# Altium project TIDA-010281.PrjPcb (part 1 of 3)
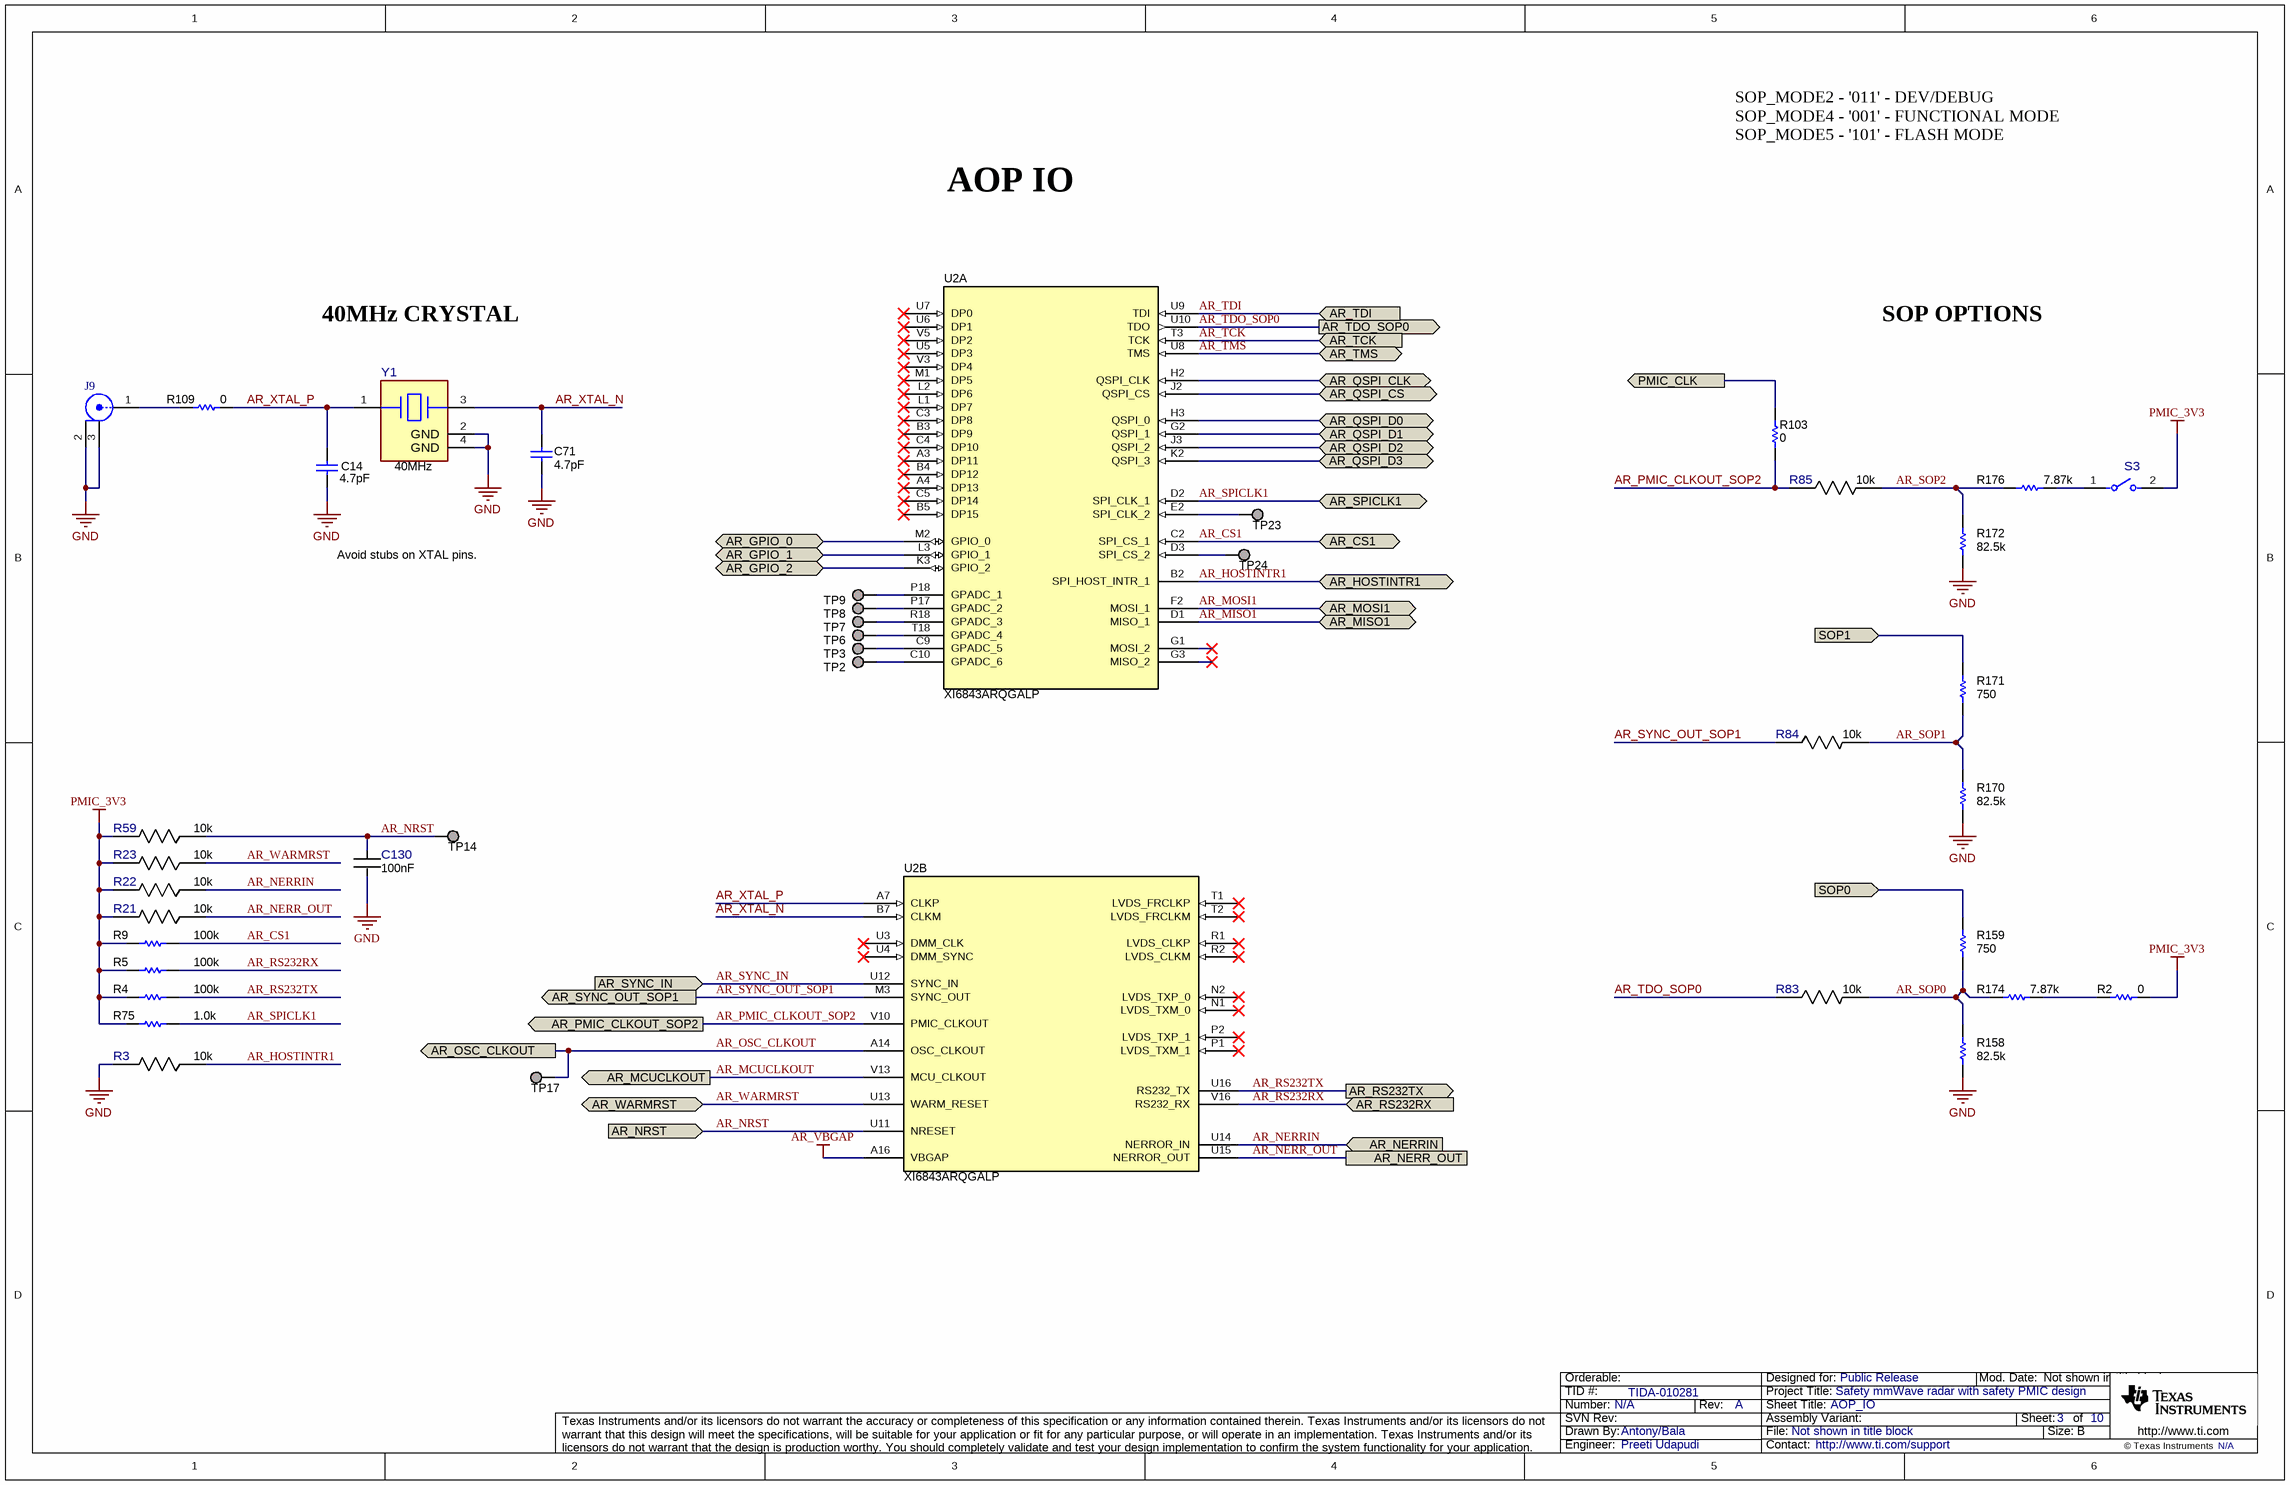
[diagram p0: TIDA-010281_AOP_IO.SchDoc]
CopyrightYear: N/A; PCB_Layout: Preeti Udapudi; PCB_Rev: A; PRJ_Customer: Public Release; PRJ_Engineer: Preeti Udapudi; PRJ_Number: N/A; PRJ_Title: Safety mmWave radar with safety PMIC design; SCH_Rev: A; TechSupport: http://www.ti.com/support; TID: TIDA-010281
10 sheets, 299 parts. Net scope: flat (ports and power ports of the same name join across sheets).
Board file: TIDA-010281.PcbDoc
Sheets:
  TIDA-010281_AOP_IO.SchDoc
  TIDA-010281_AOP_PWR.SchDoc
  TIDA-010281_BLOCK_DIAGRAM.SchDoc
  TIDA-010281_FLASH_USB_SOP.SchDoc
  TIDA-010281_Hardware.schdoc
  TIDA-010281_PMIC_BUCK.SchDoc
  TIDA-010281_RST_SWITCH.SchDoc
  TIDA-010281_TABLEOFCONTENTS.SchDoc
  TIDA-010281_XDS110_interface_1A.SchDoc
  TIDA-010281_XDS110_interface_1B.SchDoc

## Sheet TIDA-010281_AOP_IO.SchDoc: AOP_IO
size 431 x 279 mm; Date: Not shown in title block; ApprovedBy: Not shown in title block; CheckedBy: Not shown in title block; Author: Not shown in title block; CompanyName: Not shown in title block; DrawnBy: Antony/Bala; Engineer: Not shown in title block; Organization: Not shown in title block; Address1: Not shown in title block; Address2: Not shown in title block; Address3: Not shown in title block; Address4: Not shown in title block; DocumentNumber: 3; Revision: Use project parameter SCH_Rev; SheetNumber: 3; SheetTotal: 10; PageSetup: Record=PageOptions¦CenterHorizontal=True¦CenterVertical=True¦PrintScale=1.00¦XCorrection=1.00¦YCorrection=1.00¦PrintKind=0¦BorderSize=5000000¦LeftOffset=0¦BottomOffset=0¦Orientation=2¦PaperLength=1000¦PaperWidth=1000¦Scale=100¦PaperSource=15¦PrintQuality=600¦MediaType=1¦DitherType=10¦PaperKind=Letter¦PrintScaleMode=1

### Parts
C14  value 4.7pF  [0201_033L]  (hidden comment: GRM0335C1H4R7BA01D)
C71  value 4.7pF  [0201_033L]  (hidden comment: GRM0335C1H4R7BA01D)
C130  Cap_F: 100nF  [FP-GRM033R6YA104KE14D_0201 (0603 Metric)-IPC_C]  (hidden comment: GRM033R6YA104KE14D)
J9  U.FL-R-SMT-1(01)  [CONN_UFL-R-SMT-1]  (value not drawn)
R2  Res_ohm: 0  [FP-RC0201JR-070RL_0201 (0603 Metric)-MFG]  (hidden comment: RC0201JR-070RL)
R3  Res_ohm: 10k  [FP-RR0306P-103-D_0201-IPC_C]  (hidden comment: RR0306P-103-D)
R4  value 100k  [0201L]  (hidden comment: CRCW0201100KFKED)
R5  value 100k  [0201L]  (hidden comment: CRCW0201100KFKED)
R9  value 100k  [0201L]  (hidden comment: CRCW0201100KFKED)
R21  Res_ohm: 10k  [FP-RR0306P-103-D_0201-IPC_C]  (hidden comment: RR0306P-103-D)
R22  Res_ohm: 10k  [FP-RR0306P-103-D_0201-IPC_C]  (hidden comment: RR0306P-103-D)
R23  Res_ohm: 10k  [FP-RR0306P-103-D_0201-IPC_C]  (hidden comment: RR0306P-103-D)
R59  Res_ohm: 10k  [FP-RR0306P-103-D_0201-IPC_C]  (hidden comment: RR0306P-103-D)
R75  value 1.0k  [0201L]  (hidden comment: RC0201JR-071KL)
R83  Res_ohm: 10k  [FP-RR0306P-103-D_0201-IPC_C]  (hidden comment: RR0306P-103-D)
R84  Res_ohm: 10k  [FP-RR0306P-103-D_0201-IPC_C]  (hidden comment: RR0306P-103-D)
R85  Res_ohm: 10k  [FP-RR0306P-103-D_0201-IPC_C]  (hidden comment: RR0306P-103-D)
R103  Res_ohm: 0  [FP-RC0201JR-070RL_0201 (0603 Metric)-IPC_C]  (hidden comment: RC0201JR-070RL)
R109  Res_ohm: 0  [FP-RC0201JR-070RL_0201 (0603 Metric)-MFG]  (hidden comment: RC0201JR-070RL)
R158  value 82.5k  [0201L]  (hidden comment: RC0201FR-0782K5L)
R159  value 750  [0201L]  (hidden comment: RC0201JR-07750RL)
R170  value 82.5k  [0201L]  (hidden comment: RC0201FR-0782K5L)
R171  value 750  [0201L]  (hidden comment: RC0201JR-07750RL)
R172  value 82.5k  [0201L]  (hidden comment: RC0201FR-0782K5L)
R174  value 7.87k  [0201L]  (hidden comment: RC0201FR-077K87L)
R176  value 7.87k  [0201L]  (hidden comment: RC0201FR-077K87L)
S3  CHS-01TA  [FP-CHS-01TA_SMT_SW_5MM4_2MM5-MFG]  (value not drawn)
TP2  TESTPOINT  [TP_25MIL-SMT]  (value not drawn)  (no BOM)
TP3  TESTPOINT  [TP_25MIL-SMT]  (value not drawn)  (no BOM)
TP6  TESTPOINT  [TP_25MIL-SMT]  (value not drawn)  (no BOM)
TP7  TESTPOINT  [TP_25MIL-SMT]  (value not drawn)  (no BOM)
TP8  TESTPOINT  [TP_25MIL-SMT]  (value not drawn)  (no BOM)
TP9  TESTPOINT  [TP_25MIL-SMT]  (value not drawn)  (no BOM)
TP14  TESTPOINT  [TP_25MIL-SMT]  (value not drawn)  (no BOM)
TP17  TESTPOINT  [TP_25MIL-SMT]  (value not drawn)  (no BOM)
TP23  TESTPOINT  [TP_25MIL-SMT]  (value not drawn)  (no BOM)
TP24  TESTPOINT  [TP_25MIL-SMT]  (value not drawn)  (no BOM)
U2  XI6843ARQGALP  [ALP0180A]  (parts A,B of 4)
Y1  Frequency_Fixed: 40MHz  [FP-CX2016DB40000D0FLJCC_SMT_2MM0_1MM6-MFG]  (hidden comment: CX2016DB40000D0FLJCC)

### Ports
AR_CS1 (bidir), AR_GPIO_0 (bidir), AR_GPIO_1 (bidir), AR_GPIO_2 (bidir), AR_HOSTINTR1 (bidir), AR_MCUCLKOUT (out), AR_MISO1 (bidir), AR_MOSI1 (bidir), AR_NERR_OUT, AR_NERRIN (in), AR_NRST (in), AR_OSC_CLKOUT (out), AR_PMIC_CLKOUT_SOP2 (out), AR_QSPI_CLK (bidir), AR_QSPI_CS (bidir), AR_QSPI_D0 (bidir), AR_QSPI_D1 (bidir), AR_QSPI_D2 (bidir), AR_QSPI_D3 (bidir), AR_RS232RX (in), AR_RS232TX (out), AR_SPICLK1 (bidir), AR_SYNC_IN (in), AR_SYNC_OUT_SOP1 (out), AR_TCK (in), AR_TDI (in), AR_TDO_SOP0 (out), AR_TMS (bidir), AR_WARMRST (bidir), PMIC_CLK (out), SOP0 (in), SOP1 (in)

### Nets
AR_VBGAP: U2.A16(VBGAP)
GND: C14.1 C71.1 C130.2 J9.2 J9.3 R3.2 R158.1 R170.1 R172.1 Y1.2(GND) Y1.4(GND)
PMIC_3V3: R2.1 R4.1 R5.1 R9.1 R21.2 R22.2 R23.2 R59.2 R75.1 S3.2
AR_CS1: R9.2 U2.C2(SPI_CS_1) ; port AR_CS1
AR_GPIO_0: U2.M2(GPIO_0) ; port AR_GPIO_0
AR_GPIO_1: U2.L3(GPIO_1) ; port AR_GPIO_1
AR_GPIO_2: U2.K3(GPIO_2) ; port AR_GPIO_2
AR_HOSTINTR1: R3.1 U2.B2(SPI_HOST_INTR_1) ; port AR_HOSTINTR1
AR_MCUCLKOUT: U2.V13(MCU_CLKOUT) ; port AR_MCUCLKOUT
AR_MISO1: U2.D1(MISO_1) ; port AR_MISO1
AR_MOSI1: U2.F2(MOSI_1) ; port AR_MOSI1
AR_NERR_OUT: R21.1 U2.U15(NERROR_OUT) ; port AR_NERR_OUT
AR_NERRIN: R22.1 U2.U14(NERROR_IN) ; port AR_NERRIN
AR_NRST: C130.1 R59.1 TP14.1 U2.U11(NRESET) ; port AR_NRST
AR_OSC_CLKOUT: TP17.1 U2.A14(OSC_CLKOUT) ; port AR_OSC_CLKOUT
AR_PMIC_CLKOUT_SOP2: R85.1 R103.1 U2.V10(PMIC_CLKOUT) ; port AR_PMIC_CLKOUT_SOP2
AR_QSPI_CLK: U2.H2(QSPI_CLK) ; port AR_QSPI_CLK
AR_QSPI_CS: U2.J2(QSPI_CS) ; port AR_QSPI_CS
AR_QSPI_D0: U2.H3(QSPI_0) ; port AR_QSPI_D0
AR_QSPI_D1: U2.G2(QSPI_1) ; port AR_QSPI_D1
AR_QSPI_D2: U2.J3(QSPI_2) ; port AR_QSPI_D2
AR_QSPI_D3: U2.K2(QSPI_3) ; port AR_QSPI_D3
AR_RS232RX: R5.2 U2.V16(RS232_RX) ; port AR_RS232RX
AR_RS232TX: R4.2 U2.U16(RS232_TX) ; port AR_RS232TX
AR_SOP0: R83.2 R158.2 R159.1 R174.2
AR_SOP1: R84.2 R170.2 R171.1
AR_SOP2: R85.2 R172.2 R176.2
AR_SPICLK1: R75.2 U2.D2(SPI_CLK_1) ; port AR_SPICLK1
AR_SYNC_IN: U2.U12(SYNC_IN) ; port AR_SYNC_IN
AR_SYNC_OUT_SOP1: R84.1 U2.M3(SYNC_OUT) ; port AR_SYNC_OUT_SOP1
AR_TCK: U2.T3(TCK) ; port AR_TCK
AR_TDI: U2.U9(TDI) ; port AR_TDI
AR_TDO_SOP0: R83.1 U2.U10(TDO) ; port AR_TDO_SOP0
AR_TMS: U2.U8(TMS) ; port AR_TMS
AR_WARMRST: R23.1 U2.U13(WARM_RESET) ; port AR_WARMRST
AR_XTAL_N: C71.2 U2.B7(CLKM) Y1.3
AR_XTAL_P: C14.2 R109.1 U2.A7(CLKP) Y1.1
PMIC_CLK: R103.2 ; port PMIC_CLK
SOP0: R159.2 ; port SOP0
SOP1: R171.2 ; port SOP1
NetJ9_1: J9.1 R109.2
NetR2_2: R2.2 R174.1
NetR176_1: R176.1 S3.1
NetTP2_1: TP2.1 U2.C10(GPADC_6)
NetTP3_1: TP3.1 U2.C9(GPADC_5)
NetTP6_1: TP6.1 U2.T18(GPADC_4)
NetTP7_1: TP7.1 U2.R18(GPADC_3)
NetTP8_1: TP8.1 U2.P17(GPADC_2)
NetTP9_1: TP9.1 U2.P18(GPADC_1)
NetTP23_1: TP23.1 U2.E2(SPI_CLK_2)
NetTP24_1: TP24.1 U2.D3(SPI_CS_2)

Not connected (* = marked no-connect by the designer): U2 A3(DP11)* A4(DP13)* B3(DP9)* B4(DP12)* B5(DP15)* C3(DP8)* C4(DP10)* C5(DP14)* G1(MOSI_2)* G3(MISO_2)* L1(DP7)* L2(DP6)* M1(DP5)* N1(LVDS_TXM_0)* N2(LVDS_TXP_0)* P1(LVDS_TXM_1)* P2(LVDS_TXP_1)* R1(LVDS_CLKP)* R2(LVDS_CLKM)* T1(LVDS_FRCLKP)* T2(LVDS_FRCLKM)* U3(DMM_CLK)* U4(DMM_SYNC)* U5(DP3)* U6(DP1)* U7(DP0)* V3(DP4)* V5(DP2)*

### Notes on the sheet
- SOP_MODE2 - '011' - DEV/DEBUG
  SOP_MODE4 - '001' - FUNCTIONAL MODE
  SOP_MODE5 - '101' - FLASH MODE
- AOP IO
- 40MHz CRYSTAL
- SOP OPTIONS
- Avoid stubs on XTAL pins.

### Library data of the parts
C14 C71 = CMP-0080076-1: CAP, CERM, 4.7 pF, 50 V,+/- 3%, C0G/NP0, 0201; Manufacturer: MuRata; AEC Category: Q200; AEC Qualified: N; Cap_Case: 0201; SizeArea_mm2: 0.18; SizeAreaWB_mm2: 2.08; SizeX_mm: 0.6; SizeY_mm: 0.3; SizeZ_mm: 0.33; TaMax_C: 125°C; TaMin_C: -55°C; U/M: EA; Value2: 50V
C130 = CMP-0086440-1: Cap Ceramic 0.1uF 35V X5R 10% Pad SMD 0201 85C T/R; Manufacturer: Murata Electronics North America; AEC Qualified: No; SizeZ_mm: 0.33mm; Symbol Name: SYM-GRM033R6YA104KE14D; TempCo: 15%
J9 = CMP-0075320-1: Receptacle, Ultra Miniature Coaxial, Male Pin, 50 ohm, SMT; Manufacturer: Hirose Electric Co. Ltd.; CNHeader: False; Gender: Female; ContactFinish: Gold
R2 R103 R109 = CMP-0086442-2: RES SMD 0 OHM JUMPER 1/20W 0201; Manufacturer: Yageo; AEC Qualified: No; Power_W: 50mW; SizeZ_mm: 0.26mm; TempCo: 200ppm/°C; Tolerance_%: 5%; VDC_V: 25V
R3 R21-R23 R59 R83-R85 = CMP-0088002-1: 10 kOhms ±0.5% 0.05W, 1/20W Chip Resistor 0201 (0603 Metric)  Thin Film; Manufacturer: Susumu; AEC Qualified: No; Power_W: 50mW; SizeZ_mm: 0.26mm; Symbol Name: SYM-RR0306P-103-D; TempCo: 25ppm/°C; VDC_V: 15V
R4 R5 R9 = CMP-0027261-3: RES, 100 k, 1%, 0.05 W, 0201; Manufacturer: Vishay-Dale; AEC Category: Q200; AEC Qualified: N; EIA_Code: E96; Power_W: 50mW; SizeArea_mm2: 0.18; SizeX_mm: 0.6; SizeY_mm: 0.3; SizeZ_mm: 0.26; TempCo: 100 ppm/C; Value2: 0.05W; VDC_V: 30V
R75 = CMP-0027052-1: RES, 1.0 k, 5%, 0.05 W, 0201; Manufacturer: Yageo America; AEC Category: Q200; AEC Qualified: N; EIA_Code: E24; Power_W: 50mW; Res_ohm: 1k; SizeArea_mm2: 0.18; SizeX_mm: 0.6; SizeY_mm: 0.3; SizeZ_mm: 0.26; TempCo: 200 ppm/C; U/M: EA; Value2: 0.05W; Value_Code: 1k00; VDC_V: 25V
R158 R170 R172 = CMP-0027891-1: RES, 82.5 k, 1%, 0.05 W, 0201; Manufacturer: Yageo America; AEC Category: Q200; AEC Qualified: N; EIA_Code: E96; Power_W: 50mW; SizeArea_mm2: 0.18; SizeX_mm: 0.6; SizeY_mm: 0.3; SizeZ_mm: 0.26; TempCo: 200 ppm/C; U/M: EA; Value2: 0.05W; Value_Code: 82k5; VDC_V: 25V
R159 R171 = CMP-0027165-1: RES, 750, 5%, 0.05 W, 0201; Manufacturer: Yageo America; AEC Category: Q200; AEC Qualified: N; EIA_Code: E24; Power_W: 50mW; SizeArea_mm2: 0.18; SizeX_mm: 0.6; SizeY_mm: 0.3; SizeZ_mm: 0.26; TempCo: 200 ppm/C; U/M: EA; Value2: 0.05W; Value_Code: 750R; VDC_V: 25V
R174 R176 = CMP-0027880-1: RES, 7.87 k, 1%, 0.05 W, 0201; Manufacturer: Yageo America; AEC Category: Q200; AEC Qualified: N; EIA_Code: E96; Power_W: 50mW; SizeArea_mm2: 0.18; SizeX_mm: 0.6; SizeY_mm: 0.3; SizeZ_mm: 0.26; TempCo: 200 ppm/C; U/M: EA; Value2: 0.05W; Value_Code: 7k87; VDC_V: 25V
S3 = CMP-0087181-1: SWITCH SLIDE DIP SPST 100MA 6V; Manufacturer: Nidec Copal Electronics; PositionCount: 1; SizeZ_mm: 2.5mm; Symbol Name: SYM-CHS-01TA
TP2 TP3 TP6-TP9 TP14 TP17 TP23 TP24 = CMP-0078143-3: TEST POINT.  No entry in BOM.
U2 = CMP-0860942-2: XI6843ARQGALP, ALP0180A (BGA-180); Manufacturer: Texas Instruments; SizeZ_mm: 0.965; SizeX_mm: 15; AEC Qualified: N; SizeArea_mm2: 225; SizeAreaWB_mm2: 289; CompType: IC; AEC Category: Q200
Y1 = CMP-0087164-1: CRYSTAL 40.0000MHZ 8PF SMD; Manufacturer: Kyocera International Inc. Electronic Components; AEC Qualified: No; Frequency Stability: 15ppm; SizeZ_mm: 0.45mm

## Sheet TIDA-010281_AOP_PWR.SchDoc: AOP_POWER
size 431 x 279 mm; Date: Not shown in title block; ApprovedBy: Not shown in title block; CheckedBy: Not shown in title block; Author: Not shown in title block; CompanyName: Not shown in title block; DrawnBy: Antony/Bala; Engineer: Not shown in title block; Organization: Not shown in title block; Address1: Not shown in title block; Address2: Not shown in title block; Address3: Not shown in title block; Address4: Not shown in title block; DocumentNumber: 4; Revision: Use project parameter SCH_Rev; SheetNumber: 4; SheetTotal: 10; PageSetup: Record=PageOptions¦CenterHorizontal=True¦CenterVertical=True¦PrintScale=1.00¦XCorrection=1.00¦YCorrection=1.00¦PrintKind=0¦BorderSize=5000000¦LeftOffset=0¦BottomOffset=0¦Orientation=2¦PaperLength=1000¦PaperWidth=1000¦Scale=100¦PaperSource=15¦PrintQuality=600¦MediaType=1¦DitherType=10¦PaperKind=Letter¦PrintScaleMode=1
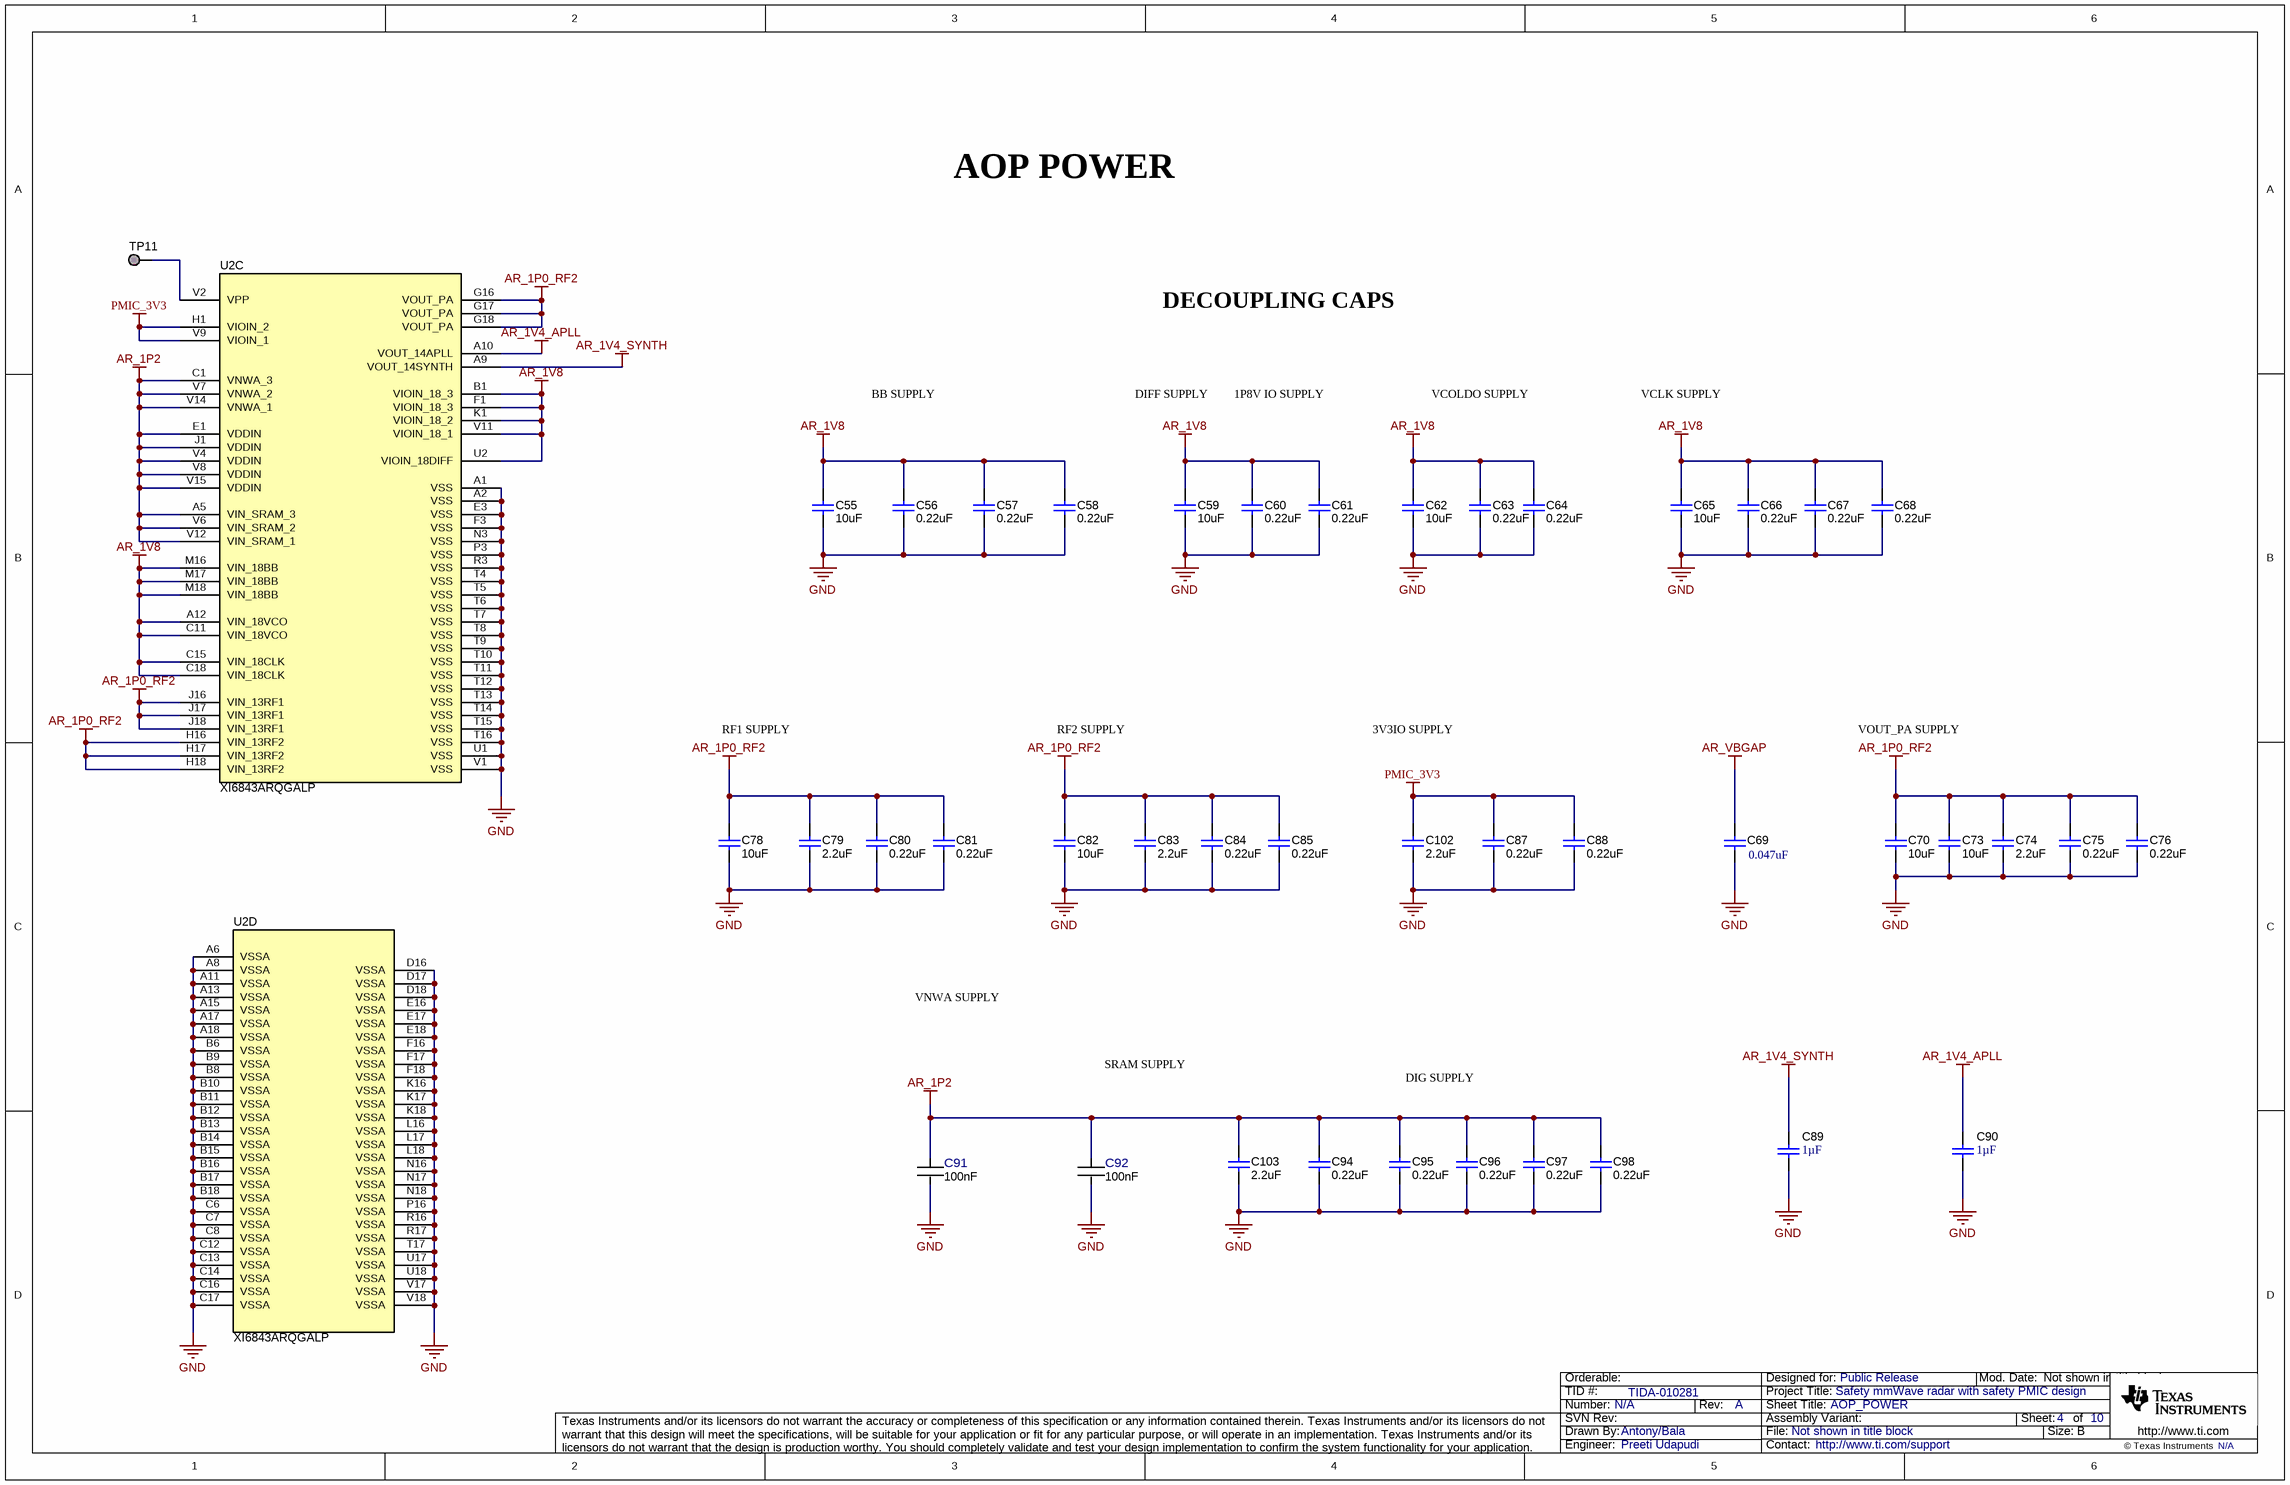
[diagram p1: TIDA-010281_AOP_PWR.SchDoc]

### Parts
C55  value 10uF  [0402_070]  (hidden comment: CL05A106MP5NUNC)
C56  value 0.22uF  [0201_033L]  (hidden comment: LMK063BJ224MP-F)
C57  value 0.22uF  [0201_033L]  (hidden comment: LMK063BJ224MP-F)
C58  value 0.22uF  [0201_033L]  (hidden comment: LMK063BJ224MP-F)
C59  value 10uF  [0402_070]  (hidden comment: CL05A106MP5NUNC)
C60  value 0.22uF  [0201_033L]  (hidden comment: LMK063BJ224MP-F)
C61  value 0.22uF  [0201_033L]  (hidden comment: LMK063BJ224MP-F)
C62  value 10uF  [0402_070]  (hidden comment: CL05A106MP5NUNC)
C63  value 0.22uF  [0201_033L]  (hidden comment: LMK063BJ224MP-F)
C64  value 0.22uF  [0201_033L]  (hidden comment: LMK063BJ224MP-F)
C65  value 10uF  [0402_070]  (hidden comment: CL05A106MP5NUNC)
C66  value 0.22uF  [0201_033L]  (hidden comment: LMK063BJ224MP-F)
C67  value 0.22uF  [0201_033L]  (hidden comment: LMK063BJ224MP-F)
C68  value 0.22uF  [0201_033L]  (hidden comment: LMK063BJ224MP-F)
C69  ValueDisplayed: 0.047uF  [0201_033L]  (hidden comment: GRM033R61C473KE84D)
C70  value 10uF  [0402_070]  (hidden comment: CL05A106MP5NUNC)
C73  value 10uF  [0402_070]  (hidden comment: CL05A106MP5NUNC)
C74  value 2.2uF  [0201L]  (hidden comment: CL03A225MQ3CRNC)
C75  value 0.22uF  [0201_033L]  (hidden comment: LMK063BJ224MP-F)
C76  value 0.22uF  [0201_033L]  (hidden comment: LMK063BJ224MP-F)
C78  value 10uF  [0402_070]  (hidden comment: CL05A106MP5NUNC)
C79  value 2.2uF  [0201L]  (hidden comment: CL03A225MQ3CRNC)
C80  value 0.22uF  [0201_033L]  (hidden comment: LMK063BJ224MP-F)
C81  value 0.22uF  [0201_033L]  (hidden comment: LMK063BJ224MP-F)
C82  value 10uF  [0402_070]  (hidden comment: CL05A106MP5NUNC)
C83  value 2.2uF  [0201L]  (hidden comment: CL03A225MQ3CRNC)
C84  value 0.22uF  [0201_033L]  (hidden comment: LMK063BJ224MP-F)
C85  value 0.22uF  [0201_033L]  (hidden comment: LMK063BJ224MP-F)
C87  value 0.22uF  [0201_033L]  (hidden comment: LMK063BJ224MP-F)
C88  value 0.22uF  [0201_033L]  (hidden comment: LMK063BJ224MP-F)
C89  ValueDisplayed: 1µF  [0402L]  (hidden comment: CGB2A1X6S0J105K033BC)
C90  ValueDisplayed: 1µF  [0402L]  (hidden comment: CGB2A1X6S0J105K033BC)
C91  Cap_F: 100nF  [FP-GRM033R6YA104KE14D_0201 (0603 Metric)-IPC_C]  (hidden comment: GRM033R6YA104KE14D)
C92  Cap_F: 100nF  [FP-GRM033R6YA104KE14D_0201 (0603 Metric)-IPC_C]  (hidden comment: GRM033R6YA104KE14D)
C94  value 0.22uF  [0201_033L]  (hidden comment: LMK063BJ224MP-F)
C95  value 0.22uF  [0201_033L]  (hidden comment: LMK063BJ224MP-F)
C96  value 0.22uF  [0201_033L]  (hidden comment: LMK063BJ224MP-F)
C97  value 0.22uF  [0201_033L]  (hidden comment: LMK063BJ224MP-F)
C98  value 0.22uF  [0201_033L]  (hidden comment: LMK063BJ224MP-F)
C102  value 2.2uF  [0201L]  (hidden comment: CL03A225MQ3CRNC)
C103  value 2.2uF  [0201L]  (hidden comment: CL03A225MQ3CRNC)
TP11  TP_SM_1MM  [TP_SM_1MM]  (value not drawn)  (no BOM)
U2  XI6843ARQGALP  [ALP0180A]  (parts C,D of 4)

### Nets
AR_1P0_RF2: C70.1 C73.1 C74.1 C75.1 C76.1 C78.1 C79.1 C80.1 C81.1 C82.1 C83.1 C84.1 C85.1 U2.G16(VOUT_PA) U2.G17(VOUT_PA) U2.G18(VOUT_PA) U2.H16(VIN_13RF2) U2.H17(VIN_13RF2) U2.H18(VIN_13RF2) U2.J16(VIN_13RF1) U2.J17(VIN_13RF1) U2.J18(VIN_13RF1)
AR_1P2: C91.1 C92.1 C94.1 C95.1 C96.1 C97.1 C98.1 C103.1 U2.A5(VIN_SRAM_3) U2.C1(VNWA_3) U2.E1(VDDIN) U2.J1(VDDIN) U2.V4(VDDIN) U2.V6(VIN_SRAM_2) U2.V7(VNWA_2) U2.V8(VDDIN) U2.V12(VIN_SRAM_1) U2.V14(VNWA_1) U2.V15(VDDIN)
AR_1V4_APLL: C90.1 U2.A10(VOUT_14APLL)
AR_1V4_SYNTH: C89.1 U2.A9(VOUT_14SYNTH)
AR_1V8: C55.1 C56.1 C57.1 C58.1 C59.1 C60.1 C61.1 C62.1 C63.1 C64.1 C65.1 C66.1 C67.1 C68.1 U2.A12(VIN_18VCO) U2.B1(VIOIN_18_3) U2.C11(VIN_18VCO) U2.C15(VIN_18CLK) U2.C18(VIN_18CLK) U2.F1(VIOIN_18_3) U2.K1(VIOIN_18_2) U2.M16(VIN_18BB) U2.M17(VIN_18BB) U2.M18(VIN_18BB) U2.U2(VIOIN_18DIFF) U2.V11(VIOIN_18_1)
AR_VBGAP: C69.1
GND: C55.2 C56.2 C57.2 C58.2 C59.2 C60.2 C61.2 C62.2 C63.2 C64.2 C65.2 C66.2 C67.2 C68.2 C69.2 C70.2 C73.2 C74.2 C75.2 C76.2 C78.2 C79.2 C80.2 C81.2 C82.2 C83.2 C84.2 C85.2 C87.2 C88.2 C89.2 C90.2 C91.2 C92.2 C94.2 C95.2 C96.2 C97.2 C98.2 C102.2 C103.2 U2.A1(VSS) U2.A2(VSS) U2.A6(VSSA) U2.A8(VSSA) U2.A11(VSSA) U2.A13(VSSA) U2.A15(VSSA) U2.A17(VSSA) U2.A18(VSSA) U2.B6(VSSA) U2.B8(VSSA) U2.B9(VSSA) U2.B10(VSSA) U2.B11(VSSA) U2.B12(VSSA) U2.B13(VSSA) U2.B14(VSSA) U2.B15(VSSA) U2.B16(VSSA) U2.B17(VSSA) U2.B18(VSSA) U2.C6(VSSA) U2.C7(VSSA) U2.C8(VSSA) U2.C12(VSSA) U2.C13(VSSA) U2.C14(VSSA) U2.C16(VSSA) U2.C17(VSSA) U2.D16(VSSA) U2.D17(VSSA) U2.D18(VSSA) U2.E3(VSS) U2.E16(VSSA) U2.E17(VSSA) U2.E18(VSSA) U2.F3(VSS) U2.F16(VSSA) U2.F17(VSSA) U2.F18(VSSA) U2.K16(VSSA) U2.K17(VSSA) U2.K18(VSSA) U2.L16(VSSA) U2.L17(VSSA) U2.L18(VSSA) U2.N3(VSS) U2.N16(VSSA) U2.N17(VSSA) U2.N18(VSSA) U2.P3(VSS) U2.P16(VSSA) U2.R3(VSS) U2.R16(VSSA) U2.R17(VSSA) U2.T4(VSS) U2.T5(VSS) U2.T6(VSS) U2.T7(VSS) U2.T8(VSS) U2.T9(VSS) U2.T10(VSS) U2.T11(VSS) U2.T12(VSS) U2.T13(VSS) U2.T14(VSS) U2.T15(VSS) U2.T16(VSS) U2.T17(VSSA) U2.U1(VSS) U2.U17(VSSA) U2.U18(VSSA) U2.V1(VSS) U2.V17(VSSA) U2.V18(VSSA)
PMIC_3V3: C87.1 C88.1 C102.1 U2.H1(VIOIN_2) U2.V9(VIOIN_1)
NetTP11_1: TP11.1 U2.V2(VPP)

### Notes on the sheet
- AOP POWER
- DECOUPLING CAPS
- BB SUPPLY
- DIFF SUPPLY
- 1P8V IO SUPPLY
- VCOLDO SUPPLY
- VCLK SUPPLY
- RF1 SUPPLY
- RF2 SUPPLY
- 3V3IO SUPPLY
- VOUT_PA SUPPLY
- VNWA SUPPLY
- SRAM SUPPLY
- DIG SUPPLY

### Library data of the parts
C55 C59 C62 C65 C70 C73 C78 C82 = CMP-0006339-4: CAP, CERM, 10 uF, 10 V, +/- 20%, X5R, 0402; Manufacturer: Samsung Electro-Mechanics; AEC Category: Q200; AEC Qualified: N; Cap_Case: 0402; Cap_F: 10µF; SizeArea_mm2: 0.5; SizeAreaWB_mm2: 3; SizeX_mm: 1; SizeZ_mm: 0.6; TaMax_C: 85°C; TaMin_C: -55°C; U/M: EA; Value1: Unknown; Value2: 10V
C56-C58 C60 C61 C63 C64 C66-C68 C75 C76 C80 C81 C84 C85 C87 C88 C94-C98 = CMP-0009781-1: CAP, CERM, 0.22 uF, 10 V, +/- 20%, X5R, 0201; Manufacturer: Taiyo Yuden; AEC Category: Q200; AEC Qualified: N; Cap_Case: 0201; Cap_F: 220nF; SizeArea_mm2: 0.18; SizeAreaWB_mm2: 2.08; SizeX_mm: 0.6; SizeY_mm: 0.3; SizeZ_mm: 0.33; TaMax_C: 85°C; TaMin_C: -55°C; U/M: EA; Value1: Unknown; Value2: 10V
C69 = CMP-0009718-2: CAP, CERM, 0.047 uF, 16 V, +/- 10%, X5R, 0201; Manufacturer: MuRata; TaMin_C: -55°C; Polarized: N; SizeAreaWB_mm2: 2.08; Value1: Unknown; U/M: EA; TaMax_C: 85°C; SizeZ_mm: 0.33; SizeX_mm: 0.6; SizeY_mm: 0.3; Cap_Case: 0201; Value2: 16V; SizeArea_mm2: 0.18; Cap_F: 47nF; AEC Category: Q200
C74 C79 C83 C102 C103 = CMP-0009657-3: CAP, CERM, 2.2 uF, 6.3 V, +/- 20%, X5R, 0201; Manufacturer: Samsung Electro-Mechanics; AEC Category: Q200; Cap_Case: 0201; Cap_F: 2.2µF; Polarized: N; SizeArea_mm2: 0.18; SizeAreaWB_mm2: 2.08; SizeX_mm: 0.6; SizeY_mm: 0.3; SizeZ_mm: 0.26; TaMax_C: 85°C; TaMin_C: -55°C; U/M: EA; Value1: Unknown; Value2: 6.3V
C89 C90 = CMP-0081763-1: CAP, CERM, 1 µF, 6.3 V,+/- 10%, X6S, 0402; Manufacturer: TDK; TaMin_C: -55°C; Polarized: N; SizeAreaWB_mm2: 3; U/M: EA; Value: 1uF; TaMax_C: 105°C; SizeZ_mm: 0.6; SizeX_mm: 1; SizeY_mm: 0.5; Cap_Case: 0402; Value2: 6.3V; CompType: Capacitor; AEC Category: Q200
C91 C92 = CMP-0086440-1: as C130 on sheet TIDA-010281_AOP_IO
TP11 = CMP-0003825-1: 1mm Test Point, SMT; Manufacturer: Any
U2 = CMP-0860942-2: as U2 on sheet TIDA-010281_AOP_IO

## Sheet TIDA-010281_BLOCK_DIAGRAM.SchDoc: BLOCK_DIAGRAM
size 431 x 279 mm; Date: Not shown in title block; ApprovedBy: Not shown in title block; CheckedBy: Not shown in title block; Author: Not shown in title block; CompanyName: Not shown in title block; DrawnBy: Antony/Bala; Engineer: Not shown in title block; Organization: Not shown in title block; Address1: Not shown in title block; Address2: Not shown in title block; Address3: Not shown in title block; Address4: Not shown in title block; DocumentNumber: 1; Revision: Use project parameter SCH_Rev; SheetNumber: 1; SheetTotal: 10; PageSetup: Record=PageOptions¦CenterHorizontal=True¦CenterVertical=True¦PrintScale=1.00¦XCorrection=1.00¦YCorrection=1.00¦PrintKind=0¦BorderSize=5000000¦LeftOffset=0¦BottomOffset=0¦Orientation=2¦PaperLength=1000¦PaperWidth=1000¦Scale=100¦PaperSource=15¦PrintQuality=600¦MediaType=1¦DitherType=10¦PaperKind=Letter¦PrintScaleMode=1
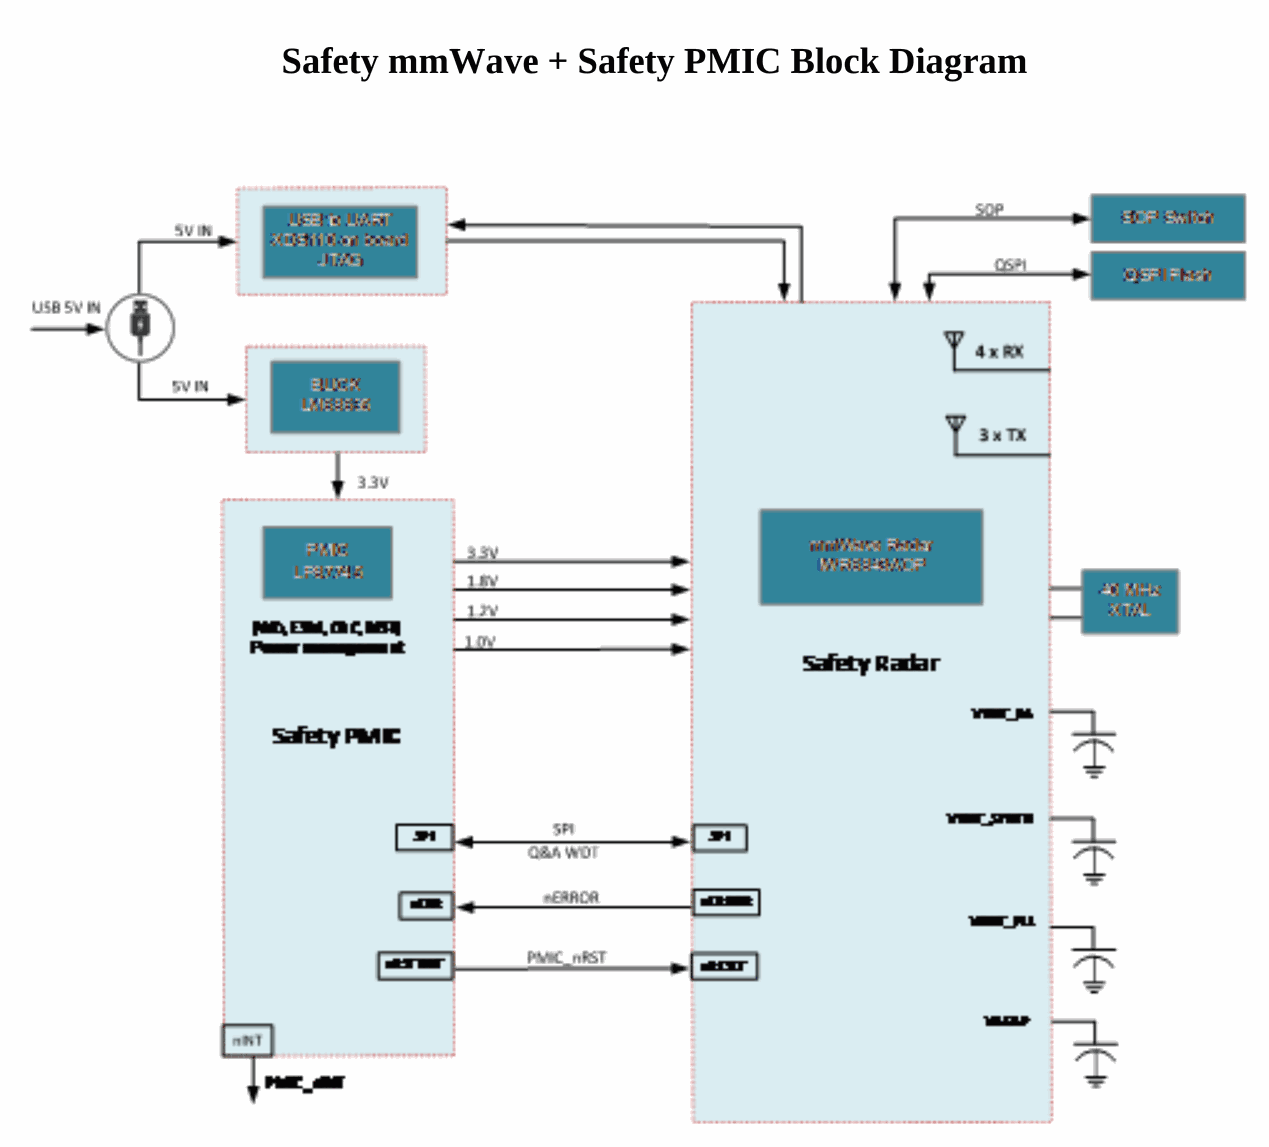
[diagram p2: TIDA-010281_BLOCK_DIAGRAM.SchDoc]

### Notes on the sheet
- Safety mmWave + Safety PMIC Block Diagram

## Sheet TIDA-010281_FLASH_USB_SOP.SchDoc: FLASH&USB_TO_UART
size 431 x 279 mm; Date: Not shown in title block; ApprovedBy: Not shown in title block; CheckedBy: Not shown in title block; Author: Not shown in title block; CompanyName: Not shown in title block; DrawnBy: Antony/Bala; Engineer: Not shown in title block; Organization: Not shown in title block; Address1: Not shown in title block; Address2: Not shown in title block; Address3: Not shown in title block; Address4: Not shown in title block; DocumentNumber: 6; Revision: Use project parameter SCH_Rev; SheetNumber: 6; SheetTotal: 10; PageSetup: Record=PageOptions¦CenterHorizontal=True¦CenterVertical=True¦PrintScale=1.00¦XCorrection=1.00¦YCorrection=1.00¦PrintKind=0¦BorderSize=5000000¦LeftOffset=0¦BottomOffset=0¦Orientation=2¦PaperLength=1000¦PaperWidth=1000¦Scale=100¦PaperSource=15¦PrintQuality=600¦MediaType=1¦DitherType=10¦PaperKind=Letter¦PrintScaleMode=1
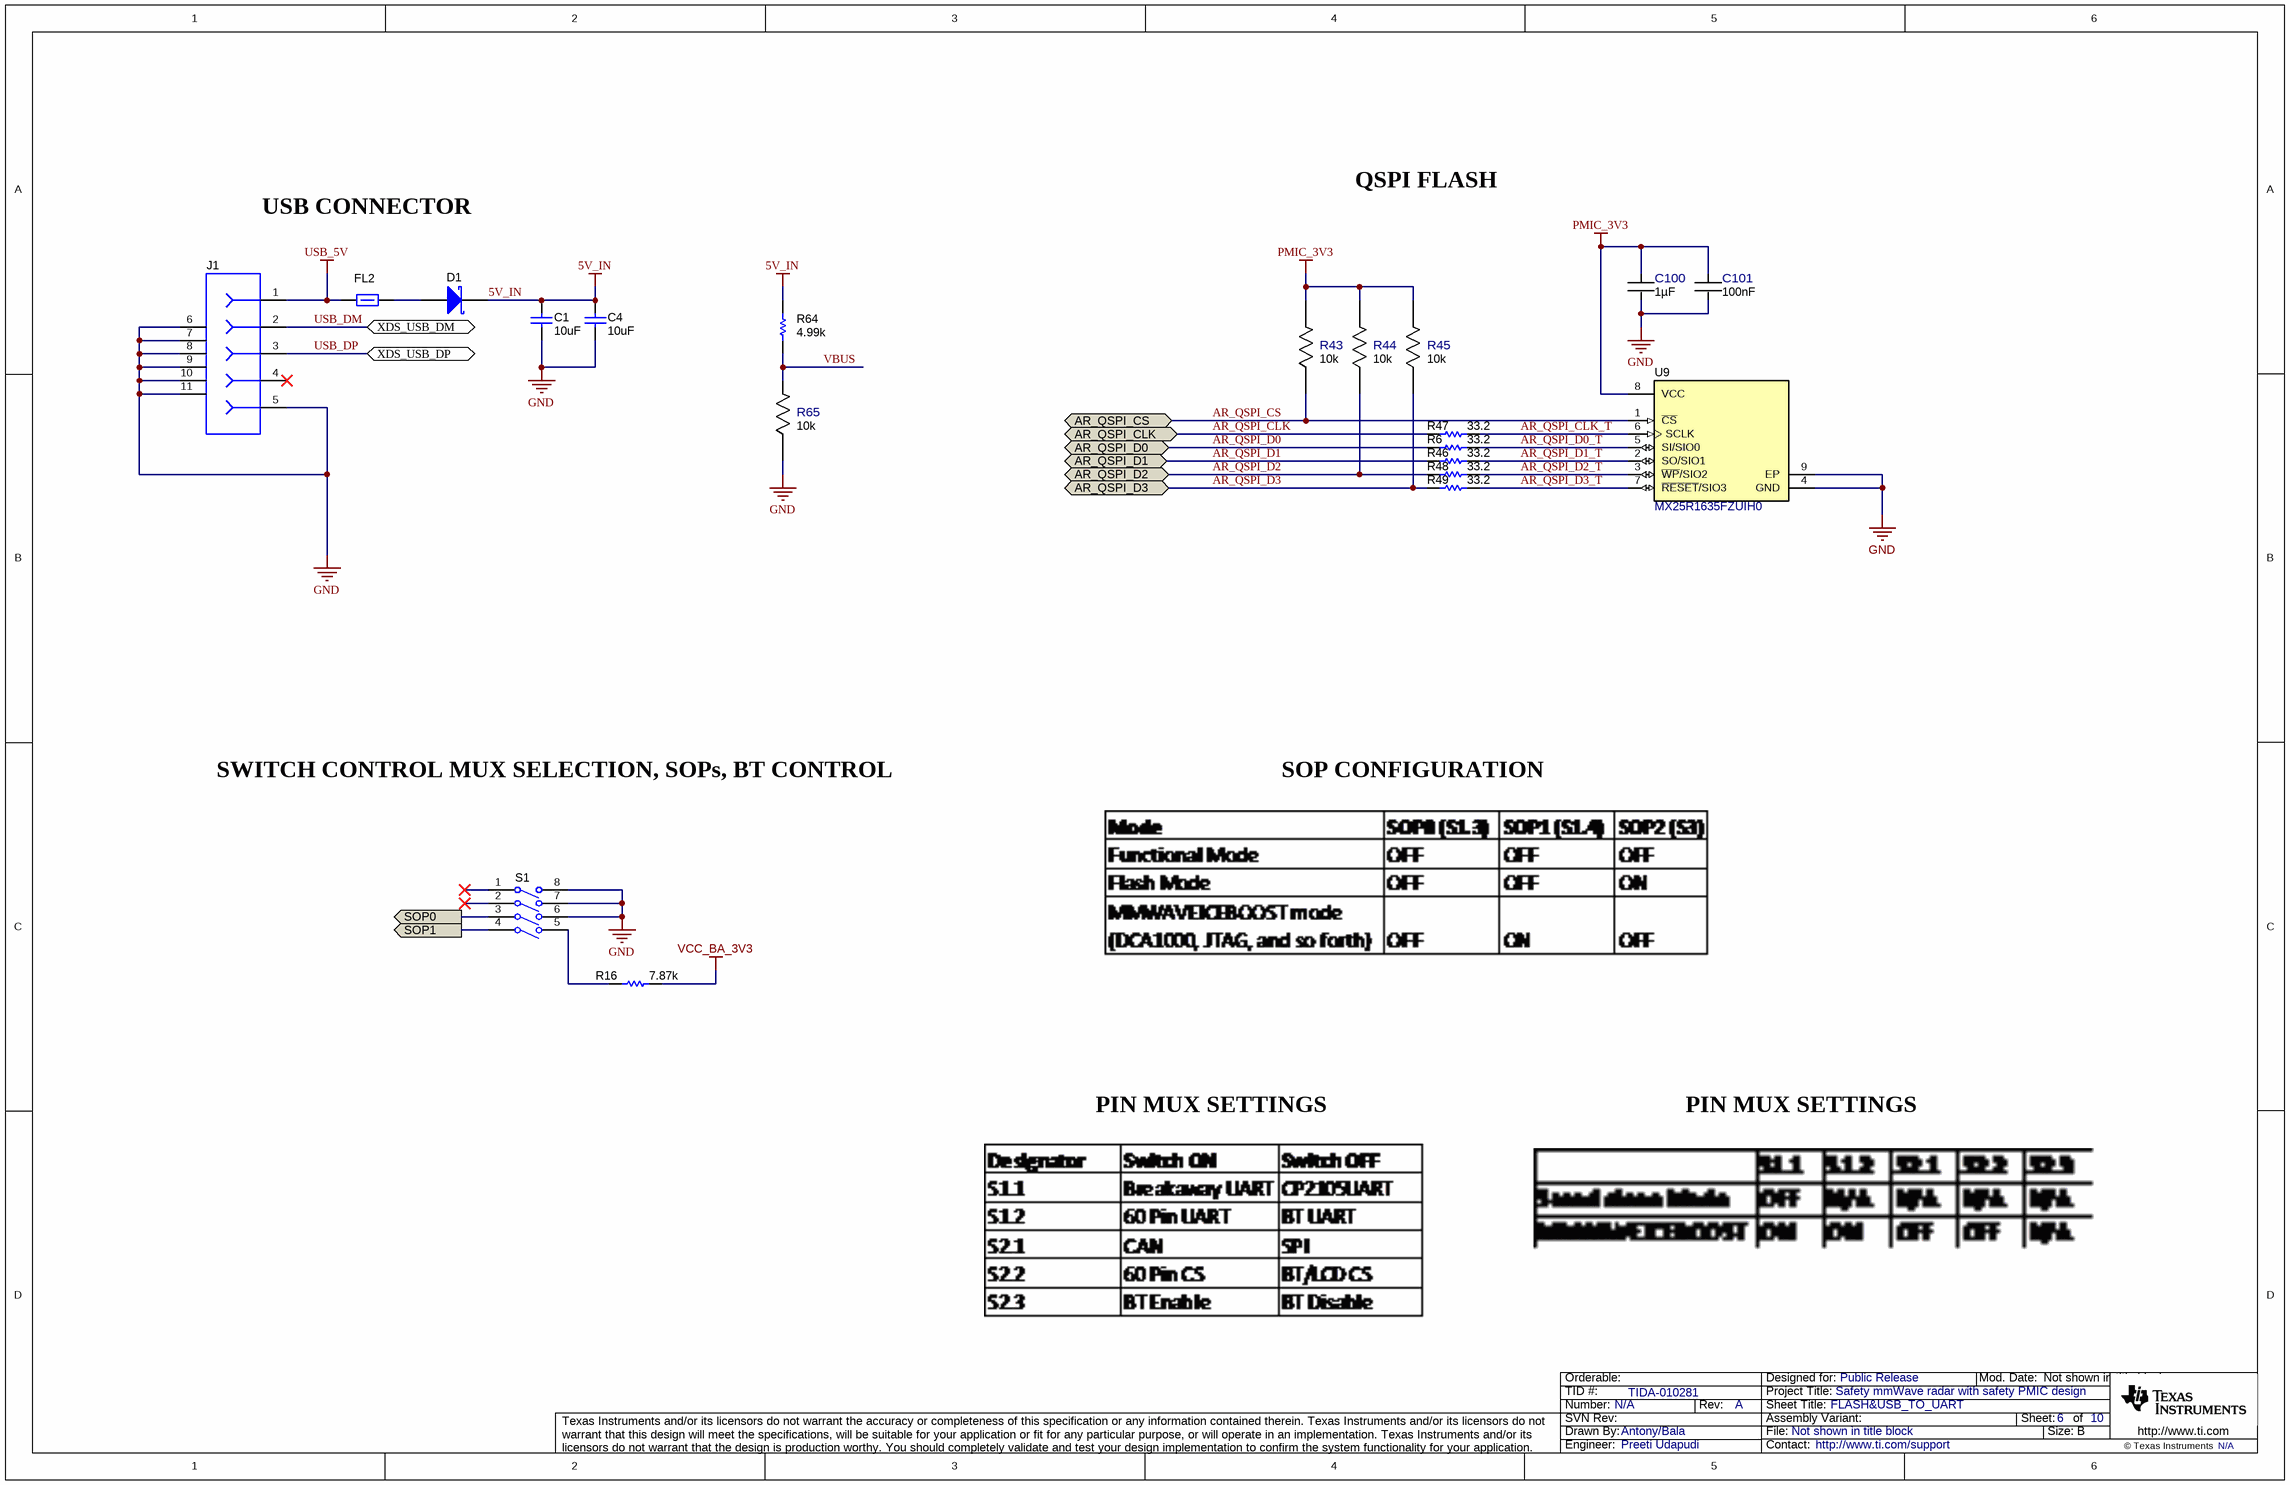
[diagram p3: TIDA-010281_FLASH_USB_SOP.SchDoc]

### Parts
C1  value 10uF  [0402_070]  (hidden comment: CL05A106MP5NUNC)
C4  value 10uF  [0402_070]  (hidden comment: CL05A106MP5NUNC)
C100  Cap_F: 1µF  [FP-CL03A105MO3NRNH_0201-IPC_C]  (hidden comment: CL03A105MO3NRNH)
C101  Cap_F: 100nF  [FP-GRM033R6YA104KE14D_0201 (0603 Metric)-IPC_C]  (hidden comment: GRM033R6YA104KE14D)
D1  NSR20F30NXT5G  [DSN2_0603]  (value not drawn)
FL2  BLM15PD300SZ1D  [0402L]  (value not drawn)
J1  105017-0001  [CONN_105017-0001]  (value not drawn)
R6  value 33.2  [0201L]  (hidden comment: CRCW020133R2FNED)
R16  value 7.87k  [0201L]  (hidden comment: RC0201FR-077K87L)
R43  Res_ohm: 10k  [FP-RR0306P-103-D_0201-IPC_C]  (hidden comment: RR0306P-103-D)
R44  Res_ohm: 10k  [FP-RR0306P-103-D_0201-IPC_C]  (hidden comment: RR0306P-103-D)
R45  Res_ohm: 10k  [FP-RR0306P-103-D_0201-IPC_C]  (hidden comment: RR0306P-103-D)
R46  value 33.2  [0201L]  (hidden comment: CRCW020133R2FNED)
R47  value 33.2  [0201L]  (hidden comment: CRCW020133R2FNED)
R48  value 33.2  [0201L]  (hidden comment: CRCW020133R2FNED)
R49  value 33.2  [0201L]  (hidden comment: CRCW020133R2FNED)
R64  value 4.99k  [0201L]  (hidden comment: RC0201FR-074K99L)
R65  Res_ohm: 10k  [FP-RR0306P-103-D_0201-IPC_C]  (hidden comment: RR0306P-103-D)
S1  218-4LPST  [SW_218-4LPST]  (value not drawn)
U9  MX25R1635FZUIH0  [USON-8L]

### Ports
AR_QSPI_CLK (bidir), AR_QSPI_CS (bidir), AR_QSPI_D0 (bidir), AR_QSPI_D1 (bidir), AR_QSPI_D2 (bidir), AR_QSPI_D3 (bidir), SOP0 (out), SOP1 (out), XDS_USB_DM (bidir), XDS_USB_DP (bidir)

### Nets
5V_IN: C1.2 C4.1 D1.1(K) R64.1
GND: C1.1 C4.2 C100.2 C101.2 J1.5 J1.6 J1.7 J1.8 J1.9 J1.10 J1.11 R65.1 S1.6(B3) S1.7(B2) S1.8(B1) U9.4(GND) U9.9(EP)
PMIC_3V3: C100.1 C101.1 R43.2 R44.2 R45.2 U9.8(VCC)
USB_5V: FL2.1 J1.1
VCC_BA_3V3: R16.1
AR_QSPI_CLK: R47.1 ; port AR_QSPI_CLK
AR_QSPI_CLK_T: R47.2 U9.6(SCLK)
AR_QSPI_CS: R43.1 U9.1(~{CS}) ; port AR_QSPI_CS
AR_QSPI_D0: R6.1 ; port AR_QSPI_D0
AR_QSPI_D0_T: R6.2 U9.5(SI/SIO0)
AR_QSPI_D1: R46.1 ; port AR_QSPI_D1
AR_QSPI_D1_T: R46.2 U9.2(SO/SIO1)
AR_QSPI_D2: R44.1 R48.1 ; port AR_QSPI_D2
AR_QSPI_D2_T: R48.2 U9.3(~{WP}/SIO2)
AR_QSPI_D3: R45.1 R49.1 ; port AR_QSPI_D3
AR_QSPI_D3_T: R49.2 U9.7(~{RESET}/SIO3)
SOP0: S1.3(A3) ; port SOP0
SOP1: S1.4(A4) ; port SOP1
USB_DM: J1.2 ; port XDS_USB_DM
USB_DP: J1.3 ; port XDS_USB_DP
VBUS: R64.2 R65.2
NetD1_2: D1.2(A) FL2.2
NetR16_2: R16.2 S1.5(B4)

Not connected (* = marked no-connect by the designer): J1 4*; S1 1(A1)* 2(A2)*

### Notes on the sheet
- USB CONNECTOR
- QSPI FLASH
- SWITCH CONTROL MUX SELECTION, SOPs, BT CONTROL
- SOP CONFIGURATION
- PIN MUX SETTINGS

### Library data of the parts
C1 C4 = CMP-0006339-4: as C55 on sheet TIDA-010281_AOP_PWR
C100 = CMP-0086446-1: 1µF ±20% 16V Ceramic Capacitor X5R 0201; Manufacturer: Samsung Electro-Mechanics; AEC Qualified: No; SizeZ_mm: 0.39mm; Symbol Name: SYM-CL03A105MO3NRNH; TempCo: 15%
C101 = CMP-0086440-1: as C130 on sheet TIDA-010281_AOP_IO
D1 = CMP-0028829-2: Diode, Schottky, 30 V, 2 A, 2-XFDFN; Manufacturer: ON Semiconductor; Value2: 0.48V; SizeY_mm: 0.8; Value: 30V; TJmax_C: 150°C; Green_Lifecycle: Not Set; SizeAreaWB_mm2: 4.68; Value1: 2A; SizeArea_mm2: 1.28; Green_REACh: Incomplete; AEC Category: Q101; SizeZ_mm: 0.31; Vf_V: 480mV; AEC Qualified: N; SizeX_mm: 1.6
FL2 = CMP-0078934-1: Inductor, Ferrite Bead, Ferrite, 2.2 A, 0.035 ohm, AEC-Q200 Grade 1, SMD; Manufacturer: MuRata; AEC Category: Q200; AEC Grade: 1; AEC Qualified: Y; DCR_ohm: 0.035; Imax_A: 2.2A; SizeArea_mm2: 0.5; SizeAreaWB_mm2: 3; SizeZ_mm: 0.6
J1 = CMP-0055293-1: Connector, Receptacle, Micro-USB Type B, R/A, Bottom Mount SMT; Manufacturer: Molex; CNHeader: FALSE; CompType: USB; CT: TRUE; Gender: Female; Green_Lifecycle: Active; Green_REACh: Passed
R6 R46-R49 = CMP-0027275-3: RES, 33.2, 1%, 0.05 W, 0201; Manufacturer: Vishay-Dale; AEC Category: Q200; AEC Qualified: N; EIA_Code: E96; Power_W: 50mW; SizeArea_mm2: 0.18; SizeX_mm: 0.6; SizeY_mm: 0.3; SizeZ_mm: 0.26; TempCo: 200 ppm/C; Value2: 0.05W; Value_Code: 33R2
R16 = CMP-0027880-1: as R174 on sheet TIDA-010281_AOP_IO
R43-R45 R65 = CMP-0088002-1: as R3 on sheet TIDA-010281_AOP_IO
R64 = CMP-0027745-1: RES, 4.99 k, 1%, 0.05 W, 0201; Manufacturer: Yageo America; AEC Category: Q200; AEC Qualified: N; EIA_Code: E96; Power_W: 50mW; SizeArea_mm2: 0.18; SizeX_mm: 0.6; SizeY_mm: 0.3; SizeZ_mm: 0.26; TempCo: 200 ppm/C; U/M: EA; Value2: 0.05W; Value_Code: 4k99; VDC_V: 25V
S1 = CMP-0002128-2: Switch, Slide, SPST 4 poles, SMT; Manufacturer: CTS Electrocomponents; CurrentRating_mA: 25A; PositionCount: 4; VDC_V: 24V; SwitchFunction: Off-On
U9 = CMP-0078466-1: ULTRA LOW POWER, 16M-BIT [x 1/x 2/x 4] CMOS MXSMIO (SERIAL MULTI I/O) FLASH MEMORY, SON-8; Manufacturer: Macronix International Co., LTD; SizeArea_mm2: 6; SizeAreaWB_mm2: 12; SizeX_mm: 3; SizeY_mm: 2; SizeZ_mm: 0.6

## Sheet TIDA-010281_Hardware.schdoc: HARDWARE
size 431 x 279 mm; Date: Not shown in title block; ApprovedBy: Not shown in title block; CheckedBy: Not shown in title block; Author: Not shown in title block; CompanyName: Not shown in title block; DrawnBy: Antony/Bala; Engineer: Not shown in title block; Organization: Not shown in title block; Address1: Not shown in title block; Address2: Not shown in title block; Address3: Not shown in title block; Address4: Not shown in title block; DocumentNumber: 10; Revision: Use project parameter SCH_Rev; SheetNumber: 10; SheetTotal: 10; PageSetup: Record=PageOptions¦CenterHorizontal=True¦CenterVertical=True¦PrintScale=1.00¦XCorrection=1.00¦YCorrection=1.00¦PrintKind=0¦BorderSize=5000000¦LeftOffset=0¦BottomOffset=0¦Orientation=2¦PaperLength=1000¦PaperWidth=1000¦Scale=100¦PaperSource=15¦PrintQuality=600¦MediaType=1¦DitherType=10¦PaperKind=Letter¦PrintScaleMode=1
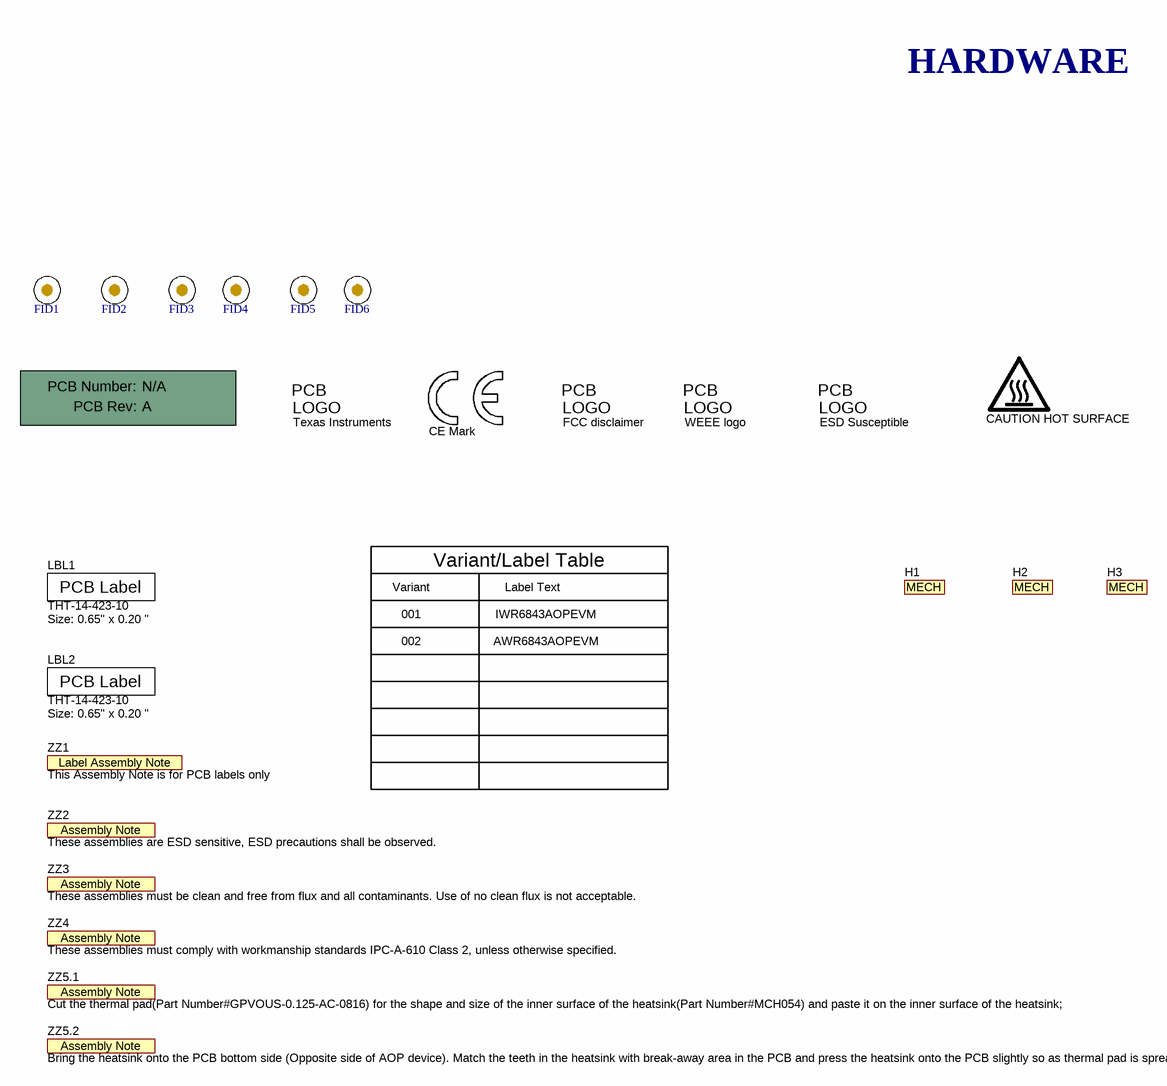
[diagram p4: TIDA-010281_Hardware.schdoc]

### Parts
!PCB  Printed Circuit Board  (value not drawn)  (mechanical)
CAUTION_HOT_SURFACE1  CAUTION HOT SURFACE  [IEC_HotSurface_Small]  (graphical)
ESD_Susceptible1  ESD Susceptible  [ESD_Overlay_Small]  (graphical)
FID1  Fiducial  [Fiducial6.4-20]  (value not drawn)
FID2  Fiducial  [Fiducial6.4-20]  (value not drawn)
FID3  Fiducial  [Fiducial6.4-20]  (value not drawn)
FID4  Fiducial  [Fiducial6.4-20]  (value not drawn)
FID5  Fiducial  [Fiducial6.4-20]  (value not drawn)
FID6  Fiducial  [Fiducial6.4-20]  (value not drawn)
H1  MechPart  (value not drawn)  (mechanical)
H2  MechPart  (value not drawn)  (mechanical)
H3  MechPart  (value not drawn)  (mechanical)
LBL1  THT-14-423-10  Note: Size: 0.65" x 0.20 "  [Label_650x200]  (graphical)
LBL2  THT-14-423-10  Note: Size: 0.65" x 0.20 "  [Label_650x200]  (graphical)
Logo1  Texas Instruments  [TI_Stacked_Overlay_Small]  (graphical)
Logo2  CE Mark  [CE_Mark_5mm]  (graphical)
Logo3  FCC disclaimer  [FCC_disclaimer]  (graphical)
Logo4  WEEE logo  [WEEE_Minimum]  (graphical)
ZZ1  This Assembly Note is for PCB labels only  [AssemblyNoteLabel]  (no BOM)
ZZ2  These assemblies are ESD sensitive, ESD precautions shall be observed.  [AssemblyNote]  (no BOM)
ZZ3  These assemblies must be clean and free from flux and all contaminants. Use of no clean flux is not acceptable.  [AssemblyNote]  (no BOM)
ZZ4  These assemblies must comply with workmanship standards IPC-A-610 Class 2, unless otherwise specified.  [AssemblyNote]  (no BOM)
ZZ5.1  Cut the thermal pad(Part Number#GPVOUS-0.125-AC-0816) for the shape and size of the inner surface of the heatsink(Part Number#MCH054) and paste it on the inner surface of the heatsink;  [AssemblyNote]  (no BOM)
ZZ5.2  Bring the heatsink onto the PCB bottom side (Opposite side of AOP device). Match the teeth in the heatsink with break-away area in the PCB and press the heatsink onto the PCB slightly so as thermal pad is spread all over the area  [AssemblyNote]  (no BOM)

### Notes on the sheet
- HARDWARE
- Variant/Label Table
- Variant
- 001
- 002
- Label Text
- IWR6843AOPEVM
- AWR6843AOPEVM

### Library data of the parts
!PCB = CMP-0003618-2: Manufacturer: Any
CAUTION_HOT_SURFACE1 = CMP-0074837-1: IEC 61010-1 Hot Surface Warning; Library Reference: IEC_HotSurface; SymbolCreator: a0412235
ESD_Susceptible1 = CMP-0074840-1: ESD Susceptible Symbol; Library Reference: Logo; SymbolCreator: a0412235; Lib Reference: ESD_Susceptible
FID1-FID6 = CMP-0077181-1: Fiducial mark.  There is nothing to buy or mount.
H1 = CMP-0080604-2: AOP EVM Heatsink; Manufacturer: Any; PartNumber: MCH054; Alternate PartNumber: 160018120021; CompType: Mechanical
H2 = CMP-0080604-2: Thermal Pad Pink 406.40mm x 203.20mm Rectangular Adhesive - One Side; Manufacturer: Bergquist; PartNumber: GPVOUS-0.125-AC-0816; CompType: Mechanical
H3 = CMP-0080604-2: xWR6843AOPEVM Mounting stand; Manufacturer: Any; PartNumber: MCH066; Alternate PartNumber: 160021010001; CompType: Mechanical
LBL1 LBL2 = CMP-0003625-1: Thermal Transfer Printable Labels, 0.650" W x 0.200" H - 10,000 per roll; Manufacturer: Brady; CompType: Label
Logo1 = CMP-0074838-1: Texas Instrument Corporate Signature; SymbolCreator: a0412235; Lib Reference: TI_Logo; Library Reference: Logo
Logo2 = CMP-0074844-1: SymbolCreator: a0412235
Logo3 = CMP-0074847-1: FCC_disclaimer; Library Reference: Logo
Logo4 = CMP-0074769-1
ZZ1 = CMP-0003616-3
ZZ2 = CMP-0077236-1
ZZ3 = CMP-0077237-1
ZZ4 ZZ5.2 = CMP-0077238-1
ZZ5.1 = CMP-0077238-1: Cut the thermal pad(Part Number#GPVOUS-0.125-AC-0816) for the shape and size of the inner surface of the heatsink(Part Number#160018120021) and paste it on the inner surface of the heatsink;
